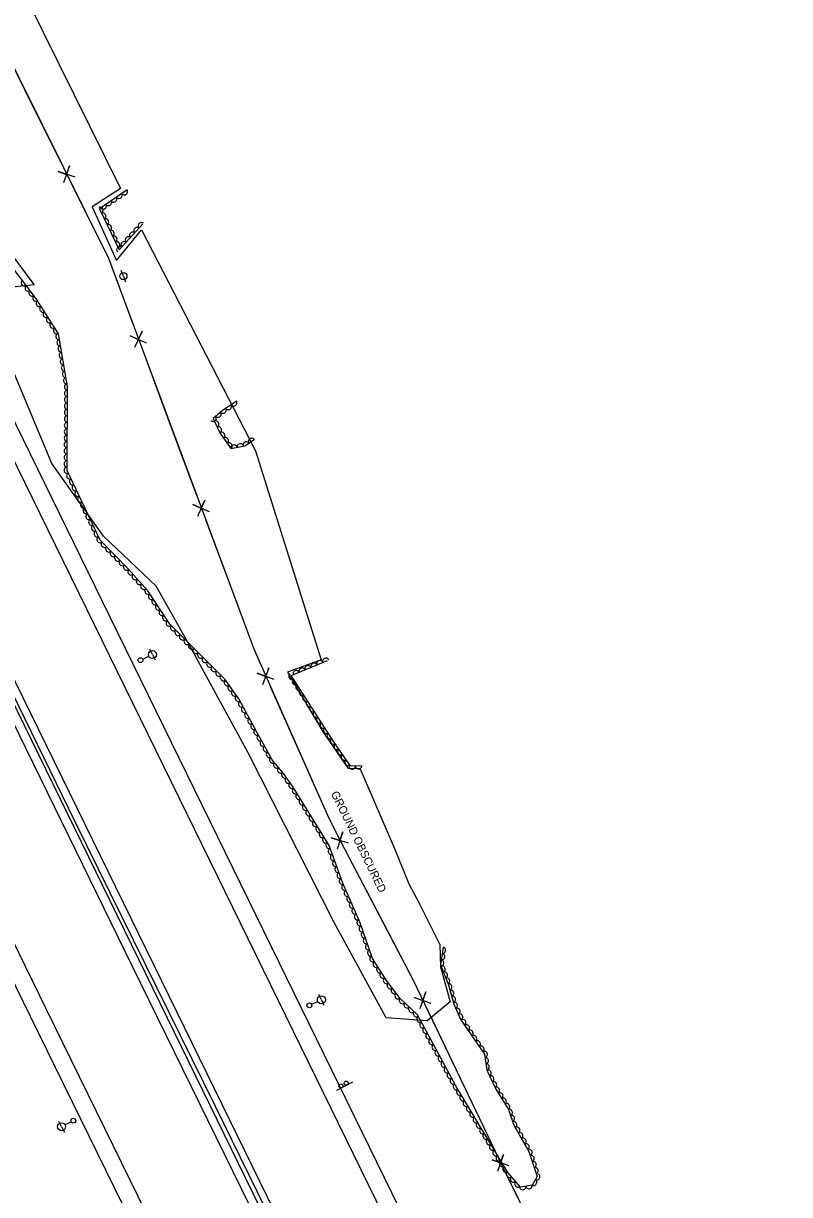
# Model space of a CAD drawing. Extents: x 1746719 to 1766531, y 631721 to 662391.
# Drawn here: x 1763928 to 1764406, y 634056 to 634788 of the extents above; entities that cross this region are included whole.
import ezdxf

# ---------------------------------------------------------------- set-up
doc = ezdxf.new("R2010")
doc.units = 0
for name, color, linetype in [('SURVEY - AERIAL SURVEY - Photo Control - Points - Elevations', 7, 'Continuous'), ('SURVEY - AERIAL SURVEY - Photo Control - Points - Locators', 7, 'Continuous'), ('SURVEY - AERIAL SURVEY - Photo Control - Points - Numbers', 7, 'Continuous'), ('SURVEY - AERIAL SURVEY - Photo Control with Text', 7, 'Continuous'), ('SURVEY - CENTERLINE - Existing Roads - Development', 7, 'Continuous'), ('SURVEY - CENTERLINE - Existing Roads Curve Text', 7, 'Continuous'), ('SURVEY - CONTROL - Grid', 7, 'Continuous')]:
    doc.layers.add(name, color=color, linetype=linetype)

msp = doc.modelspace()

# ---------------------------------------------------------------- linework, layer by layer
at = {"layer": 'SURVEY - AERIAL SURVEY - Photo Control - Points - Elevations'}
for points in [[(1764340.85, 633658.5), (1764275.78, 633792.04), (1764195.08, 633956.44), (1764073, 634206.27), (1763967.52, 634421.86), (1763841.54, 634679.29), (1763757.6, 634851.52), (1763694.9, 634979.06)], [(1764350.74, 633663.32), (1764285.66, 633796.87), (1764204.96, 633961.28), (1764082.89, 634211.1), (1763977.4, 634426.7), (1763851.43, 634684.12), (1763767.48, 634856.35), (1763704.77, 634983.91)], [(1764286.91, 633632.22), (1764221.88, 633765.68), (1764141.2, 633930.05), (1764019.1, 634179.91), (1763913.63, 634395.49), (1763787.63, 634652.96), (1763703.71, 634825.14), (1763641.05, 634952.58)], [(1763630.83, 634945.82), (1763681.1, 634843.13), (1763756.43, 634688.91), (1763840.36, 634517.91), (1763911.67, 634371.12), (1763995.88, 634198.93), (1764084.74, 634017.62), (1764168.83, 633846.36), (1764236.28, 633708.97), (1764276.55, 633626.71)], [(1763567.06, 634914.6), (1763617.31, 634811.94), (1763692.66, 634657.68), (1763776.56, 634486.76), (1763847.85, 634340.01), (1763932.12, 634167.71), (1764021, 633986.35), (1764105.09, 633815.07), (1764172.53, 633677.71), (1764180.93, 633660.56)], [(1763576.94, 634919.44), (1763627.2, 634816.77), (1763702.54, 634662.52), (1763786.44, 634491.58), (1763857.74, 634344.83), (1763942, 634172.55), (1764030.87, 633991.19), (1764114.97, 633819.92), (1764182.41, 633682.55), (1764210.63, 633624.92)]]:
    msp.add_lwpolyline(points, dxfattribs=at)
at = {"layer": 'SURVEY - AERIAL SURVEY - Photo Control - Points - Locators'}
for points in [[(1764168.59, 634250.31), (1764174.91, 634238.23), (1764187.93, 634212.5), (1764188.39, 634198.55), (1764194.23, 634176.8), (1764179.96, 634164.74), (1764154.34, 634166.62), (1764121.95, 634226.33), (1764068.32, 634332.23), (1764030.7, 634400.87), (1764010.92, 634436.23), (1763977.89, 634467.53), (1763945.66, 634512.84), (1763916.77, 634582.22), (1763902.23, 634621.03), (1763904.66, 634621.64), (1763934.6, 634624.71), (1763908.63, 634659.51), (1763861.32, 634729.36), (1763835.56, 634781.82), (1763818.39, 634801.6)], [(1763930.71, 634801.72), (1763988.62, 634684.69), (1763970.84, 634673.21), (1763986.01, 634639.62), (1764001.71, 634658.86), (1764072.82, 634520.81), (1764113.84, 634390.4), (1764092.86, 634382.58), (1764115.1, 634345.13), (1764130.64, 634322.46), (1764138.04, 634322.74), (1764159.58, 634272.4), (1764168.59, 634250.31)]]:
    msp.add_lwpolyline(points, dxfattribs=at)
at = {"layer": 'SURVEY - AERIAL SURVEY - Photo Control - Points - Numbers'}
for points in [[(1764283.41, 633629.46), (1764202.99, 633793.6), (1764120.58, 633962.6), (1764047.91, 634111.29), (1763960.25, 634289.05), (1763909.33, 634393.41), (1763836.64, 634541.81), (1763766.39, 634685.66), (1763677.3, 634867.98), (1763637.77, 634949.46)], [(1763635.49, 634947.88), (1763696.6, 634823.22), (1763800.9, 634609.62), (1763896.95, 634413.45), (1764004.19, 634194.3), (1764106.63, 633984.76), (1764197.37, 633799.63), (1764281.43, 633628.12)]]:
    msp.add_lwpolyline(points, dxfattribs=at)
at = {"layer": 'SURVEY - AERIAL SURVEY - Photo Control with Text'}
for points in [[(1763992.7, 634683.73), (1763975.37, 634672), (1763987.77, 634646.26), (1764002.56, 634662.63)], [(1764189.9, 634210.84), (1764188.29, 634199.71), (1764193.22, 634187.27), (1764196.64, 634175.18), (1764201.07, 634165.43), (1764209.3, 634153.44), (1764215.75, 634144.04), (1764217.12, 634133.96), (1764222.9, 634122.07), (1764230.72, 634109.39), (1764234.15, 634099.63), (1764243.51, 634083.18), (1764248.59, 634067.62), (1764245.46, 634062.17), (1764238.22, 634060.93), (1764230.26, 634070.17), (1764198.12, 634123.76), (1764173.95, 634168.55), (1764163.02, 634178.86), (1764154.95, 634189.32), (1764145.86, 634203.85), (1764138.06, 634226.11), (1764127.37, 634250.82), (1764118.78, 634274.24), (1764106.04, 634295.01), (1764096.34, 634310.7), (1764090.35, 634319.32), (1764083.27, 634327.88), (1764073.72, 634345.21), (1764062.37, 634365.85), (1764053.64, 634378.24), (1764042.27, 634389.66), (1764034.69, 634397.14), (1764019.42, 634412.5), (1764005.6, 634433.35), (1763993.35, 634447.19), (1763975.92, 634464.94), (1763955.23, 634508.5), (1763955.49, 634561.05), (1763949.85, 634593.88), (1763936.07, 634615.61), (1763915.76, 634642.64)], [(1764060.9, 634551.81), (1764052.21, 634545.93), (1764046.34, 634541.04), (1764050.65, 634532.15), (1764057.39, 634522.27), (1764066.09, 634523.88), (1764072.21, 634528.02)], [(1764139.17, 634324.13), (1764132.17, 634323.79), (1764120.97, 634340.34), (1764095.18, 634380.47), (1764117.85, 634389.97)]]:
    msp.add_lwpolyline(points, dxfattribs=at)
for centre, major_axis in [((1763984.41, 634678.12), (-1.66, -1.12)), ((1763987.73, 634680.37), (-1.66, -1.12)), ((1763991.04, 634682.61), (-1.66, -1.12)), ((1763975.83, 634671.03), (0.87, -1.8)), ((1763977.79, 634673.64), (-1.66, -1.12)), ((1763981.1, 634675.88), (-1.66, -1.12)), ((1763977.57, 634667.43), (0.87, -1.8)), ((1763979.31, 634663.83), (0.87, -1.8)), ((1764001.51, 634661.47), (1.34, 1.48)), ((1763981.04, 634660.22), (0.87, -1.8)), ((1763982.78, 634656.62), (0.87, -1.8)), ((1763996.15, 634655.54), (1.34, 1.48)), ((1763998.83, 634658.5), (1.34, 1.48)), ((1763984.51, 634653.02), (0.87, -1.8)), ((1763986.25, 634649.41), (0.87, -1.8)), ((1763990.78, 634649.6), (1.34, 1.48)), ((1763993.47, 634652.57), (1.34, 1.48)), ((1763988.1, 634646.63), (1.34, 1.48)), ((1763928.46, 634625.73), (-1.2, 1.6)), ((1763930.87, 634622.53), (-1.2, 1.6)), ((1763933.27, 634619.33), (-1.2, 1.6)), ((1763935.67, 634616.14), (-1.2, 1.6)), ((1763937.86, 634612.79), (-1.07, 1.69)), ((1763940, 634609.41), (-1.07, 1.69)), ((1763942.14, 634606.03), (-1.07, 1.69)), ((1763944.28, 634602.65), (-1.07, 1.69)), ((1763946.43, 634599.28), (-1.07, 1.69)), ((1763948.57, 634595.9), (-1.07, 1.69)), ((1763950.12, 634592.29), (-0.34, 1.97)), ((1763950.8, 634588.35), (-0.34, 1.97)), ((1763951.48, 634584.41), (-0.34, 1.97)), ((1763952.16, 634580.47), (-0.34, 1.97)), ((1763952.83, 634576.53), (-0.34, 1.97)), ((1763953.51, 634572.58), (-0.34, 1.97)), ((1763954.19, 634568.64), (-0.34, 1.97)), ((1763954.87, 634564.7), (-0.34, 1.97)), ((1763955.49, 634560.75), (0.01, 2)), ((1763955.45, 634552.75), (0.01, 2)), ((1763955.47, 634556.75), (0.01, 2)), ((1763955.41, 634544.75), (0.01, 2)), ((1763955.43, 634548.75), (0.01, 2)), ((1764052.61, 634546.2), (-1.66, -1.12)), ((1764055.93, 634548.44), (-1.66, -1.12)), ((1764059.24, 634550.69), (-1.66, -1.12)), ((1763955.39, 634540.75), (0.01, 2)), ((1764046.44, 634541.12), (-1.54, -1.28)), ((1764048.03, 634537.55), (0.87, -1.8)), ((1764049.51, 634543.68), (-1.54, -1.28)), ((1763955.35, 634532.75), (0.01, 2)), ((1763955.37, 634536.75), (0.01, 2)), ((1764049.77, 634533.95), (0.87, -1.8)), ((1764051.77, 634530.5), (1.13, -1.65)), ((1763955.31, 634524.75), (0.01, 2)), ((1763955.33, 634528.75), (0.01, 2)), ((1764054.02, 634527.2), (1.13, -1.65)), ((1764056.28, 634523.89), (1.13, -1.65)), ((1764059.39, 634522.64), (1.97, 0.36)), ((1764063.32, 634523.37), (1.97, 0.36)), ((1764067.07, 634524.55), (1.66, 1.12)), ((1764070.39, 634526.79), (1.66, 1.12)), ((1763955.27, 634516.75), (0.01, 2)), ((1763955.29, 634520.75), (0.01, 2)), ((1763955.23, 634508.75), (0.01, 2)), ((1763955.25, 634512.75), (0.01, 2)), ((1763956.84, 634505.12), (-0.86, 1.81)), ((1763958.55, 634501.5), (-0.86, 1.81)), ((1763960.27, 634497.89), (-0.86, 1.81)), ((1763961.99, 634494.28), (-0.86, 1.81)), ((1763963.7, 634490.66), (-0.86, 1.81)), ((1763965.42, 634487.05), (-0.86, 1.81)), ((1763967.13, 634483.44), (-0.86, 1.81)), ((1763968.85, 634479.82), (-0.86, 1.81)), ((1763970.57, 634476.21), (-0.86, 1.81)), ((1763972.28, 634472.6), (-0.86, 1.81)), ((1763974, 634468.98), (-0.86, 1.81)), ((1763975.71, 634465.37), (-0.86, 1.81)), ((1763978.39, 634462.43), (-1.4, 1.43)), ((1763981.19, 634459.57), (-1.4, 1.43)), ((1763983.99, 634456.72), (-1.4, 1.43)), ((1763986.8, 634453.87), (-1.4, 1.43)), ((1763989.6, 634451.01), (-1.4, 1.43)), ((1763992.4, 634448.16), (-1.4, 1.43)), ((1763995.11, 634445.21), (-1.32, 1.5)), ((1763997.76, 634442.21), (-1.32, 1.5)), ((1764000.4, 634439.22), (-1.32, 1.5)), ((1764003.05, 634436.22), (-1.32, 1.5)), ((1764005.69, 634433.21), (-1.11, 1.67)), ((1764007.9, 634429.88), (-1.11, 1.67)), ((1764010.11, 634426.54), (-1.11, 1.67)), ((1764012.32, 634423.21), (-1.11, 1.67)), ((1764014.53, 634419.88), (-1.11, 1.67)), ((1764016.74, 634416.54), (-1.11, 1.67)), ((1764018.95, 634413.21), (-1.11, 1.67)), ((1764021.64, 634410.27), (-1.41, 1.42)), ((1764024.46, 634407.43), (-1.41, 1.42)), ((1764027.28, 634404.59), (-1.41, 1.42)), ((1764030.1, 634401.76), (-1.41, 1.42)), ((1764032.92, 634398.92), (-1.41, 1.42)), ((1764035.75, 634396.09), (-1.42, 1.4)), ((1764038.6, 634393.28), (-1.42, 1.4)), ((1764041.45, 634390.48), (-1.42, 1.4)), ((1764044.28, 634387.65), (-1.41, 1.42)), ((1764047.1, 634384.81), (-1.41, 1.42)), ((1764105.6, 634384.84), (1.84, 0.77)), ((1764109.29, 634386.39), (1.84, 0.77)), ((1764112.98, 634387.93), (1.84, 0.77)), ((1764116.67, 634389.48), (1.84, 0.77)), ((1764049.92, 634381.98), (-1.41, 1.42)), ((1764052.74, 634379.14), (-1.41, 1.42)), ((1764095.55, 634379.88), (-1.08, 1.68)), ((1764098.23, 634381.74), (1.84, 0.77)), ((1764101.92, 634383.29), (1.84, 0.77)), ((1764055.21, 634376.01), (-1.15, 1.63)), ((1764057.51, 634372.74), (-1.15, 1.63)), ((1764059.82, 634369.47), (-1.15, 1.63)), ((1764097.72, 634376.52), (-1.08, 1.68)), ((1764099.88, 634373.15), (-1.08, 1.68)), ((1764102.04, 634369.79), (-1.08, 1.68)), ((1764062.12, 634366.2), (-1.15, 1.63)), ((1764064.09, 634362.72), (-0.96, 1.75)), ((1764104.21, 634366.42), (-1.08, 1.68)), ((1764106.37, 634363.06), (-1.08, 1.68)), ((1764066.02, 634359.22), (-0.96, 1.75)), ((1764067.94, 634355.71), (-0.96, 1.75)), ((1764108.53, 634359.69), (-1.08, 1.68)), ((1764110.7, 634356.33), (-1.08, 1.68)), ((1764069.87, 634352.21), (-0.96, 1.75)), ((1764071.8, 634348.7), (-0.96, 1.75)), ((1764112.86, 634352.96), (-1.08, 1.68)), ((1764115.02, 634349.6), (-1.08, 1.68)), ((1764073.73, 634345.2), (-0.97, 1.75)), ((1764075.66, 634341.69), (-0.97, 1.75)), ((1764117.18, 634346.24), (-1.08, 1.68)), ((1764119.35, 634342.87), (-1.08, 1.68)), ((1764077.59, 634338.19), (-0.97, 1.75)), ((1764079.52, 634334.69), (-0.97, 1.75)), ((1764121.53, 634339.52), (-1.12, 1.66)), ((1764123.77, 634336.21), (-1.12, 1.66)), ((1764126.01, 634332.89), (-1.12, 1.66)), ((1764081.45, 634331.18), (-0.97, 1.75)), ((1764083.42, 634327.7), (-1.27, 1.54)), ((1764128.25, 634329.58), (-1.12, 1.66)), ((1764130.5, 634326.27), (-1.12, 1.66)), ((1764085.96, 634324.62), (-1.27, 1.54)), ((1764088.51, 634321.54), (-1.27, 1.54)), ((1764090.99, 634318.4), (-1.14, 1.64)), ((1764133.18, 634323.84), (-2, -0.1)), ((1764137.17, 634324.04), (-2, -0.1)), ((1764093.27, 634315.12), (-1.14, 1.64)), ((1764095.56, 634311.83), (-1.14, 1.64)), ((1764097.72, 634308.47), (-1.05, 1.7)), ((1764099.82, 634305.07), (-1.05, 1.7)), ((1764101.93, 634301.67), (-1.05, 1.7)), ((1764104.03, 634298.26), (-1.05, 1.7)), ((1764106.13, 634294.86), (-1.05, 1.7)), ((1764108.22, 634291.45), (-1.05, 1.7)), ((1764110.31, 634288.04), (-1.05, 1.7)), ((1764112.41, 634284.63), (-1.05, 1.7)), ((1764114.5, 634281.22), (-1.05, 1.7)), ((1764116.59, 634277.81), (-1.05, 1.7)), ((1764118.68, 634274.4), (-1.05, 1.7)), ((1764120.09, 634270.66), (-0.69, 1.88)), ((1764121.47, 634266.91), (-0.69, 1.88)), ((1764122.84, 634263.15), (-0.69, 1.88)), ((1764124.22, 634259.39), (-0.69, 1.88)), ((1764125.6, 634255.64), (-0.69, 1.88)), ((1764126.98, 634251.88), (-0.69, 1.88)), ((1764128.51, 634248.19), (-0.79, 1.84)), ((1764130.1, 634244.52), (-0.79, 1.84)), ((1764131.68, 634240.85), (-0.79, 1.84)), ((1764133.27, 634237.18), (-0.79, 1.84)), ((1764134.86, 634233.51), (-0.79, 1.84)), ((1764136.45, 634229.83), (-0.79, 1.84)), ((1764138.04, 634226.16), (-0.79, 1.84)), ((1764139.36, 634222.39), (-0.66, 1.89)), ((1764140.68, 634218.61), (-0.66, 1.89)), ((1764142.01, 634214.84), (-0.66, 1.89)), ((1764143.33, 634211.06), (-0.66, 1.89)), ((1764189.62, 634208.86), (-0.29, -1.98)), ((1764144.65, 634207.29), (-0.66, 1.89)), ((1764146.04, 634203.55), (-1.06, 1.7)), ((1764188.47, 634200.95), (-0.29, -1.98)), ((1764189.04, 634204.9), (-0.29, -1.98)), ((1764148.17, 634200.16), (-1.06, 1.7)), ((1764150.29, 634196.77), (-1.06, 1.7)), ((1764189.3, 634197.15), (0.74, -1.86)), ((1764190.78, 634193.43), (0.74, -1.86)), ((1764152.41, 634193.38), (-1.06, 1.7)), ((1764154.53, 634189.99), (-1.06, 1.7)), ((1764156.91, 634186.77), (-1.22, 1.58)), ((1764192.25, 634189.71), (0.74, -1.86)), ((1764193.59, 634185.95), (0.54, -1.92)), ((1764159.36, 634183.61), (-1.22, 1.58)), ((1764161.8, 634180.44), (-1.22, 1.58)), ((1764194.68, 634182.1), (0.54, -1.92)), ((1764164.48, 634177.49), (-1.46, 1.37)), ((1764167.39, 634174.74), (-1.46, 1.37)), ((1764195.77, 634178.25), (0.54, -1.92)), ((1764196.97, 634174.45), (0.83, -1.82)), ((1764170.3, 634172), (-1.46, 1.37)), ((1764173.21, 634169.25), (-1.46, 1.37)), ((1764175.37, 634165.93), (-0.95, 1.76)), ((1764198.63, 634170.8), (0.83, -1.82)), ((1764200.28, 634167.16), (0.83, -1.82)), ((1764177.27, 634162.41), (-0.95, 1.76)), ((1764179.17, 634158.89), (-0.95, 1.76)), ((1764202.25, 634163.7), (1.13, -1.65)), ((1764204.52, 634160.4), (1.13, -1.65)), ((1764206.78, 634157.1), (1.13, -1.65)), ((1764181.06, 634155.37), (-0.95, 1.76)), ((1764182.96, 634151.85), (-0.95, 1.76)), ((1764209.05, 634153.81), (1.13, -1.65)), ((1764211.31, 634150.51), (1.13, -1.65)), ((1764184.86, 634148.33), (-0.95, 1.76)), ((1764186.76, 634144.81), (-0.95, 1.76)), ((1764213.57, 634147.21), (1.13, -1.65)), ((1764215.77, 634143.89), (0.27, -1.98)), ((1764188.66, 634141.29), (-0.95, 1.76)), ((1764190.56, 634137.77), (-0.95, 1.76)), ((1764216.31, 634139.92), (0.27, -1.98)), ((1764216.85, 634135.96), (0.27, -1.98)), ((1764192.46, 634134.25), (-0.95, 1.76)), ((1764194.36, 634130.73), (-0.95, 1.76)), ((1764217.99, 634132.18), (0.87, -1.8)), ((1764219.74, 634128.58), (0.87, -1.8)), ((1764196.26, 634127.21), (-0.95, 1.76)), ((1764198.16, 634123.69), (-1.03, 1.72)), ((1764221.49, 634124.98), (0.87, -1.8)), ((1764223.3, 634121.42), (1.05, -1.7)), ((1764200.22, 634120.26), (-1.03, 1.72)), ((1764202.28, 634116.83), (-1.03, 1.72)), ((1764204.33, 634113.4), (-1.03, 1.72)), ((1764225.4, 634118.02), (1.05, -1.7)), ((1764227.5, 634114.61), (1.05, -1.7)), ((1764206.39, 634109.97), (-1.03, 1.72)), ((1764208.45, 634106.54), (-1.03, 1.72)), ((1764229.6, 634111.21), (1.05, -1.7)), ((1764231.34, 634107.63), (0.66, -1.89)), ((1764210.51, 634103.11), (-1.03, 1.72)), ((1764212.56, 634099.68), (-1.03, 1.72)), ((1764232.66, 634103.86), (0.66, -1.89)), ((1764233.99, 634100.08), (0.66, -1.89)), ((1764214.62, 634096.25), (-1.03, 1.72)), ((1764216.68, 634092.82), (-1.03, 1.72)), ((1764235.89, 634096.57), (0.99, -1.74)), ((1764237.87, 634093.09), (0.99, -1.74)), ((1764218.74, 634089.39), (-1.03, 1.72)), ((1764220.79, 634085.95), (-1.03, 1.72)), ((1764239.85, 634089.62), (0.99, -1.74)), ((1764241.83, 634086.14), (0.99, -1.74)), ((1764222.85, 634082.52), (-1.03, 1.72)), ((1764224.91, 634079.09), (-1.03, 1.72)), ((1764243.69, 634082.61), (0.62, -1.9)), ((1764244.94, 634078.81), (0.62, -1.9)), ((1764226.96, 634075.66), (-1.03, 1.72)), ((1764229.02, 634072.23), (-1.03, 1.72)), ((1764246.18, 634075.01), (0.62, -1.9)), ((1764247.42, 634071.21), (0.62, -1.9)), ((1764231.3, 634068.96), (-1.31, 1.51)), ((1764233.91, 634065.93), (-1.31, 1.51)), ((1764236.52, 634062.9), (-1.31, 1.51)), ((1764246.48, 634063.96), (-1, -1.73)), ((1764248.47, 634067.42), (-1, -1.73)), ((1764239.6, 634061.17), (-1.97, -0.34)), ((1764243.54, 634061.84), (-1.97, -0.34))]:
    msp.add_ellipse(centre, major_axis=major_axis, ratio=0.940188, start_param=0, end_param=3.141593, dxfattribs=at)
at = {"layer": 'SURVEY - CENTERLINE - Existing Roads - Development'}
for p, q in [((1763990.35, 634629.92), (1763988.99, 634633.41)), ((1763990.35, 634629.92), (1763991.71, 634626.42)), ((1764008.51, 634393.6), (1764006.91, 634396.98)), ((1764008.51, 634393.6), (1764010.12, 634390.21)), ((1764002.42, 634390.7), (1764006.26, 634392.52)), ((1764113.93, 634177.97), (1764112.36, 634181.38)), ((1764107.8, 634175.15), (1764111.66, 634176.93)), ((1764113.93, 634177.97), (1764115.5, 634174.57)), ((1763951.8, 634098.68), (1763950.07, 634102.01)), ((1763957.79, 634101.78), (1763954.02, 634099.83)), ((1763951.8, 634098.68), (1763953.52, 634095.35))]:
    msp.add_line(p, q, dxfattribs=at)
for centre, radius in [((1763990.35, 634629.92), 2.25), ((1764008.51, 634393.6), 2.5), ((1764001.06, 634390.06), 1.5), ((1764106.44, 634174.52), 1.5), ((1764113.93, 634177.97), 2.5), ((1763951.8, 634098.68), 2.5), ((1763959.12, 634102.47), 1.5)]:
    msp.add_circle(centre, radius, dxfattribs=at)
at = {"layer": 'SURVEY - CENTERLINE - Existing Roads Curve Text'}
for points in [[(1763780.02, 635048.91), (1763815.95, 634974.29), (1763882.51, 634839.7), (1763981, 634641.08), (1764071.7, 634397.09), (1764118.55, 634291.37), (1764126.02, 634276.66), (1764171.26, 634190.33), (1764227.21, 634073.36), (1764288.57, 633947.89), (1764347.68, 633826.17), (1764406.17, 633707.92)], [(1763908.34, 634787.62), (1763928.95, 634746.05)], [(1763928.95, 634746.05), (1763951.16, 634701.25)], [(1763960.25, 634691.7), (1763949.58, 634695.22), (1763954.94, 634693.41), (1763956.74, 634698.77), (1763953.08, 634688.14)], [(1763958.31, 634686.83), (1763978.93, 634645.26)], [(1763978.93, 634645.26), (1763981, 634641.08), (1763996.79, 634598.58)], [(1764004.84, 634588.13), (1763994.59, 634592.75), (1763999.73, 634590.4), (1764002.09, 634595.54), (1763997.34, 634585.35)], [(1764002.41, 634583.49), (1764018.57, 634540)], [(1764018.57, 634540), (1764036, 634493.14)], [(1764044.04, 634482.68), (1764033.79, 634487.3), (1764038.93, 634484.95), (1764041.29, 634490.09), (1764036.54, 634479.9)], [(1764041.6, 634478.04), (1764057.77, 634434.55)], [(1764057.77, 634434.55), (1764071.7, 634397.09), (1764075.76, 634387.92)], [(1764084.43, 634377.98), (1764073.92, 634381.96), (1764079.2, 634379.92), (1764081.23, 634385.2), (1764077.12, 634374.74)], [(1764082.29, 634373.2), (1764101.08, 634330.78)], [(1764101.08, 634330.78), (1764118.55, 634291.37), (1764121.67, 634285.22)], [(1764130.86, 634275.75), (1764120.15, 634279.17), (1764125.52, 634277.42), (1764127.28, 634282.8), (1764123.73, 634272.13)], [(1764129.04, 634270.91), (1764150.57, 634229.81)], [(1764150.57, 634229.81), (1764171.26, 634190.33), (1764173.6, 634185.43)], [(1764182.56, 634175.74), (1764171.93, 634179.42), (1764177.27, 634177.54), (1764179.15, 634182.87), (1764175.34, 634172.29)], [(1764180.55, 634170.9), (1764200.57, 634129.05)], [(1764200.57, 634129.05), (1764222.15, 634083.94)], [(1764231.11, 634074.26), (1764220.48, 634077.93), (1764225.81, 634076.05), (1764227.7, 634081.39), (1764223.89, 634070.81)], [(1764229.13, 634069.44), (1764249.52, 634027.75)]]:
    msp.add_lwpolyline(points, dxfattribs=at)
at = {"layer": 'SURVEY - CONTROL - Grid'}
msp.add_line((1764133.37, 634126.59), (1764123.46, 634121.38), dxfattribs=at)
for centre in [(1764126.1, 634124.15), (1764129.42, 634125.9)]:
    msp.add_circle(centre, 1.25, dxfattribs=at)

# ---------------------------------------------------------------- texts
at = {"layer": 'SURVEY - AERIAL SURVEY - Photo Control - Points - Locators'}
msp.add_text('GROUND OBSCURED', height=5, rotation=295.9917, dxfattribs=at).set_placement((1764119.8, 634306.84))

doc.saveas('drawing.dxf')
